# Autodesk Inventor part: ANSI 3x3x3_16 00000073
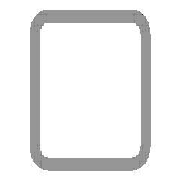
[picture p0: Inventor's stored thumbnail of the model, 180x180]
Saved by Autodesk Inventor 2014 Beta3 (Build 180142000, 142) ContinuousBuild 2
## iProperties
IsCustomPart: 1
_CCFamilyMember: 9
_CCFamilyDisplayName: ANSI AISC (Square) - Tube
_FrameMemberDoc: Frame Member File
_Version: 15.0.0
_GetPNFromCC: 1
Created: 2011-01
Part Number: ANSI 3x3x3_16 00000073
Material: Steel, Mild
Description: Tube
Document SubType Name: Modeling
Standard: ANSI
Designer: Beta-8540w
Standards Organization: ANSI
Language: en-US
Size Designation: 3x3x3/16
Categories: <MemberInstance><Categories><Category DisplayName="Structural Shapes" InternalName="089c4875-fa83-4c05-b084-43b9cc11f5ed" Mnemonic="GRDR"><CategoryParameter Dis
Stock Number: 3x3x3/16
Density: 7.86 g/cm^3
Appearance: Steel
G_L: 58.775 in
G_W: 3.000 in
G_H: 3.000 in
+F1DD31D7-8EA7-4030-B73F-B4109CE49B1F+CUTDETAIL1: Cut
Author: Beta-8540w
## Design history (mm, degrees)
node "Start plane"
node "End plane"
sketch "Sketch"
  geometry: L1 (-38.1, -28.575)-(-38.1, 28.575); L2 (-28.575, 38.1)-(28.575, 38.1); L3 (38.1, 28.575)-(38.1, -28.575); L4 (28.575, -38.1)-(-28.575, -38.1); L5 (-28.575, 33.337)-(28.575, 33.338); L6 (33.338, 28.575)-(33.338, -28.575); L7 (28.575, -33.337)-(-28.575, -33.338); L8 (-33.338, -28.575)-(-33.338, 28.575); L9 (0, 56.102)-(0, -56.102) reference; L10 (-56.102, 0)-(56.102, 0) reference; A1 r 9.525 centre (-28.575, -28.575) between (-38.1, -28.575) and (-28.575, -38.1); A2 r 9.525 centre (-28.575, 28.575) between (-28.575, 38.1) and (-38.1, 28.575); A3 r 9.525 centre (28.575, 28.575) between (38.1, 28.575) and (28.575, 38.1); A4 r 9.525 centre (28.575, -28.575) between (28.575, -38.1) and (38.1, -28.575); A5 r 4.763 centre (-28.575, 28.575) between (-28.575, 33.337) and (-33.338, 28.575); A6 r 4.763 centre (28.575, 28.575) between (33.338, 28.575) and (28.575, 33.338); A7 r 4.763 centre (28.575, -28.575) between (28.575, -33.337) and (33.338, -28.575); A8 r 4.763 centre (-28.575, -28.575) between (-33.338, -28.575) and (-28.575, -33.338)
  constraints: 16 end point, 16 point on circle, 8 centre point, 8 tangent, 4 parallel, 3 equal radius, 2 perpendicular, 7 other
  dimensions: "d10" = 76.2 distance between parallel lines of L2 L4 (= G_H); "d11" = 76.2 distance between parallel lines of L1 L3 (= G_W); "d12" = 4.7625 distance between parallel lines of L3 L6 (= G_T); "d15" = 38.1 distance between parallel lines of L2 L10 (= 0.5 x d10); "d16" = 38.1 distance between parallel lines of L9 L3 (= 0.5 x d11); "d17" = 9.525 radius of A1 (= G_IR)
extrude "Body" new body sketch "Sketch" stored distance "d3" = 1492.89148 (= G_L); taper "d4" = 0 deg
node "Driven Length"
  sketch "Sketch3"
    geometry: L1 (0, 0)-(10, 0) reference
    constraints: 2 end point, 1 horizontal
  workplane "Work Plane3"
  sketch "Sketch4"
    geometry: L1 (-2, 31.109)-(12, 31.109) reference; L2 (-2, 1524)-(12, 1524) reference
    dimensions: "d19" = 1492.89148 distance between parallel lines of L1 L2 (derived)
workplane "Work Plane4"
split "Split1"
body "Solid1"
other parameters: "G_W" = 76.2 [user parameter; used in 1 equation term], "G_H" = 76.2 [user parameter; used in 1 equation term], "G_T" = 4.7625 [user parameter; used in 1 equation term], "G_IR" = 9.525 [user parameter; used in 1 equation term], "G_L" = 1492.89148 (= d19) [user parameter; used in 1 equation term], "G_OFFSET_START" = -31.10852 [user parameter; used in 1 equation term], "G_OFFSET_END" = 0 [user parameter; used in 1 equation term], "d13" = 31.10852 (= -G_OFFSET_START), "d14" = 1524 (= G_OFFSET_END + B_L), "B_L" = 1524 [user parameter; used in 1 equation term], "d18" = 90 deg
